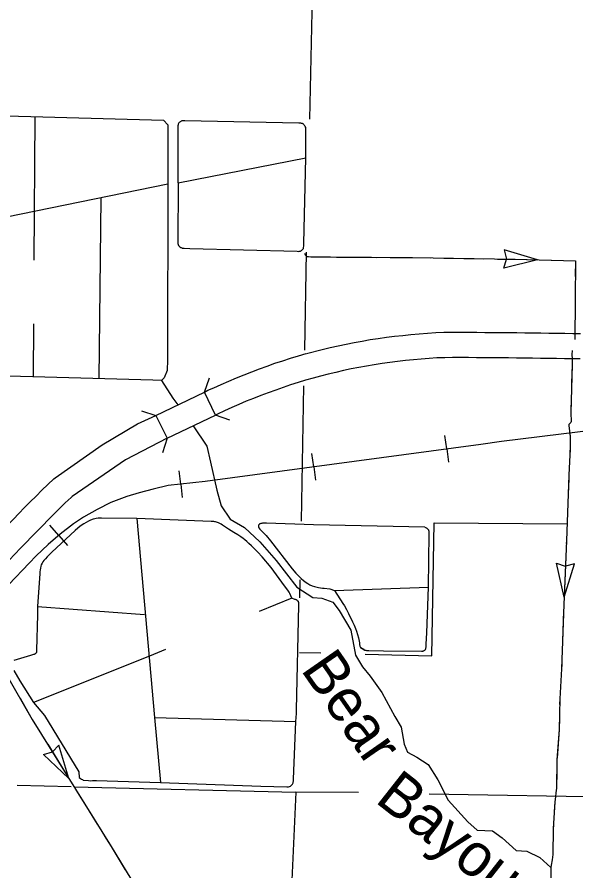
# Model space of a CAD drawing. Extents: x 1196286 to 1268366, y 2040822 to 2082115.
# Drawn here: x 1223139 to 1225200, y 2055546 to 2058695 of the extents above; entities that cross this region are included whole.
import ezdxf

# ---------------------------------------------------------------- set-up
doc = ezdxf.new("R2010")
doc.units = 0
for name, color, linetype in [('60', 7, 'Continuous'), ('62', 7, 'Continuous'), ('63', 7, 'Continuous'), ('Level 70', 7, 'Continuous'), ('Level 76', 7, 'Continuous'), ('Level 81', 7, 'Continuous'), ('Level 84', 7, 'Continuous')]:
    doc.layers.add(name, color=color, linetype=linetype)

msp = doc.modelspace()

# ---------------------------------------------------------------- linework, layer by layer
at = {"layer": '60'}
for points in [[(1224227.9, 2058772.2), (1224217.3, 2058319.1)], [(1224205.7, 2057827.8), (1224198.7, 2057466.5)], [(1224196.2, 2057334.4), (1224186.5, 2056835.4)], [(1224182.3, 2056619.6), (1224181, 2056552.5)], [(1223338.9, 2055856.2), (1223139.9, 2055860.9)], [(1226102.5, 2055804.8), (1224658.8, 2055828.4)]]:
    msp.add_lwpolyline(points, dxfattribs=at)
at = {"layer": '62'}
for points in [[(1222253.8, 2058354.1), (1223679.6, 2058314.3), (1223694.7, 2058298.1), (1223694.9, 2058089.6), (1223694.2, 2057430.3), (1223692.6, 2057391.9), (1223681.3, 2057364.7), (1223671.9, 2057354.8), (1223639.9, 2057355.7), (1222708.7, 2057381.5), (1222720.4, 2057879.5)], [(1223204.6, 2058327.6), (1223201.2, 2057798.8)], [(1224204, 2058175.4), (1224204.8, 2058277.6), (1224204.7, 2058280.9), (1224204.4, 2058284.1), (1224204.2, 2058286.1), (1224203.6, 2058288), (1224202.2, 2058291.3), (1224200.6, 2058294.2), (1224198.6, 2058296.9), (1224196.3, 2058299), (1224193.9, 2058301), (1224192.7, 2058301.6), (1224191.5, 2058302.2), (1224190, 2058302.6), (1224188.5, 2058302.9), (1224185.7, 2058303.2), (1224178.1, 2058303.6), (1223757.9, 2058312.7), (1223752.8, 2058312.9), (1223749.4, 2058312.6), (1223747.2, 2058312.1), (1223744.8, 2058311.2), (1223742.6, 2058310.1), (1223740.9, 2058309.1), (1223739.1, 2058307.7), (1223737.2, 2058305.8), (1223736.1, 2058304.4), (1223734.5, 2058302), (1223733.7, 2058300.1), (1223733.2, 2058297.7), (1223732.7, 2058294), (1223732.5, 2058289.7), (1223732.7, 2058083.6)], [(1223733.2, 2058083.7), (1223731.8, 2057862.9), (1223732.1, 2057860.8), (1223732.3, 2057859.4), (1223733.6, 2057855.9), (1223735.1, 2057853.1), (1223737.4, 2057850.1), (1223740, 2057847.7), (1223742.9, 2057845.5), (1223744.4, 2057844.6), (1223746.3, 2057843.8), (1223748.3, 2057843.1), (1223751.5, 2057842.5), (1223755.3, 2057842.3), (1223776.7, 2057841.8), (1224172.1, 2057831.2), (1224177.4, 2057830.9), (1224180.2, 2057831.1), (1224182.1, 2057831.5), (1224184, 2057832), (1224185.7, 2057832.7), (1224187.6, 2057833.7), (1224189.4, 2057834.9), (1224191.1, 2057836.1), (1224192.4, 2057837.4), (1224193.6, 2057838.8), (1224194.5, 2057840.4), (1224195, 2057841.6), (1224195.7, 2057843.7), (1224196.1, 2057845.8), (1224196.4, 2057849.9), (1224196.9, 2057860.5), (1224203.6, 2058175.3)], [(1223733.2, 2058083.7), (1224203.6, 2058175.3)], [(1223694.9, 2058078.7), (1222720.4, 2057879.5)], [(1223448.1, 2058028.3), (1223441.2, 2057361.2)], [(1223199.7, 2057564.2), (1223198.4, 2057367.9)], [(1223671.9, 2057354.8), (1223713.8, 2057289.9), (1223732, 2057264.3)], [(1223789.1, 2057187.7), (1223838.9, 2057112.5), (1223852.7, 2057052.9), (1223876.2, 2056950.3), (1223891.7, 2056892.2), (1223925.6, 2056843.3), (1223978.4, 2056813.1), (1224035.1, 2056759.9), (1224094.4, 2056690.2), (1224170.4, 2056591.9), (1224229.5, 2056554.9), (1224263.8, 2056551.8), (1224304.1, 2056537), (1224327.3, 2056506.5), (1224370.1, 2056434.4), (1224387.5, 2056341.9), (1224413.4, 2056298.2), (1224441.5, 2056264.2), (1224484.8, 2056204.2), (1224531.8, 2056115.3), (1224556.3, 2056076.5), (1224566.7, 2056013.8), (1224578.6, 2055983.8), (1224613.8, 2055965.9), (1224655.2, 2055937.9), (1224690.5, 2055882.3), (1224729.2, 2055806.9), (1224801.2, 2055726.8), (1224835.9, 2055695.8), (1224893.1, 2055693.3), (1224928, 2055667.3), (1224980.1, 2055620.8), (1225019.4, 2055619.1), (1225067.5, 2055595.7), (1225108.3, 2055558.5)], [(1223580.4, 2056845.3), (1223450.3, 2056846.5), (1223442.8, 2056846.9), (1223438.3, 2056846.6), (1223431.4, 2056845.8), (1223425.5, 2056844.7), (1223419.7, 2056843.1), (1223409.9, 2056839.8), (1223402.9, 2056835.7), (1223393.5, 2056831.1), (1223386.1, 2056826.6), (1223371.8, 2056817.1), (1223353.1, 2056801.4), (1223267.1, 2056721.4), (1223254.9, 2056709.5), (1223249.9, 2056703.8), (1223243.9, 2056697.4), (1223237.9, 2056690.3), (1223234.5, 2056686), (1223231.4, 2056680.8), (1223228.7, 2056674.6), (1223227, 2056669.7), (1223225.8, 2056662.7), (1223224.8, 2056656.9), (1223223.7, 2056648.4), (1223223.4, 2056642.5), (1223215, 2056520.8)], [(1224152.6, 2056551.6), (1224144.8, 2056568.8), (1224142.2, 2056574), (1224139.9, 2056578), (1224137.8, 2056581.1), (1224125, 2056597.7), (1224076.2, 2056665.4), (1224043.4, 2056704.5), (1224027.4, 2056721.3), (1224003.7, 2056745.1), (1223994.4, 2056753.8), (1223987, 2056760.7), (1223979, 2056767.2), (1223973, 2056771.7), (1223964.5, 2056777.9), (1223953.6, 2056785), (1223938.3, 2056794.3), (1223918.5, 2056806.1), (1223896.5, 2056821.6), (1223891.7, 2056824.8), (1223887.5, 2056827.3), (1223882.2, 2056829.5), (1223878.7, 2056830.8), (1223874.4, 2056832.2), (1223870.9, 2056833), (1223868.1, 2056833.6), (1223864.4, 2056834.1), (1223860.3, 2056834.4), (1223855.4, 2056834.5), (1223580.4, 2056845.3)], [(1223580.4, 2056845.3), (1223646.3, 2056111.4), (1223668.4, 2055871.7)], [(1224643.2, 2056813.5), (1224232.3, 2056822.4), (1224058.7, 2056828), (1224048.6, 2056828.3), (1224044.7, 2056828.1), (1224041.6, 2056827.8), (1224038.5, 2056827.2), (1224035.7, 2056826.3), (1224034.2, 2056825.5), (1224032.6, 2056824.4), (1224031.6, 2056823.5), (1224030.4, 2056822.2), (1224029.8, 2056821), (1224029.4, 2056819.3), (1224029.3, 2056817.9), (1224029.3, 2056816.4), (1224029.4, 2056815), (1224029.9, 2056813.5), (1224030.6, 2056811.9), (1224031.4, 2056810.8), (1224035, 2056806.2), (1224049.5, 2056792.1), (1224058.1, 2056782.4), (1224074.3, 2056763.6), (1224154, 2056660.5), (1224167.6, 2056644.6), (1224178.4, 2056633.2), (1224187, 2056624.7), (1224195.5, 2056617.1), (1224204.9, 2056609.9), (1224211.6, 2056605.6), (1224219.1, 2056601.5), (1224227.3, 2056597.9), (1224236.3, 2056594.8), (1224245.4, 2056592.1), (1224251, 2056590.8), (1224257.9, 2056589.7), (1224265.4, 2056588.8), (1224272.2, 2056588.4), (1224293, 2056585.9), (1224310.2, 2056579.7)], [(1224656.5, 2056592.4), (1224659, 2056789.5), (1224659, 2056793.4), (1224659.1, 2056795.6), (1224658.9, 2056797.2), (1224658.8, 2056798.5), (1224658.4, 2056799.7), (1224658.1, 2056801), (1224657.2, 2056802.5), (1224656.3, 2056803.9), (1224655.4, 2056805), (1224654.7, 2056806), (1224653, 2056807.6), (1224651.5, 2056808.7), (1224648.9, 2056810.4), (1224647.7, 2056811), (1224646.2, 2056811.7), (1224643.8, 2056812.3)], [(1224310.2, 2056579.7), (1224656.5, 2056592.4)], [(1224310.2, 2056579.7), (1224341.2, 2056532.4), (1224346.2, 2056523.9), (1224353.7, 2056510.4), (1224361.2, 2056495.2), (1224376.8, 2056464.4), (1224382.4, 2056451.7), (1224387, 2056440.3), (1224390.9, 2056429.7), (1224398, 2056405.6), (1224401.5, 2056387.2), (1224402.7, 2056380.2), (1224403.1, 2056377.7), (1224403.7, 2056375.1), (1224404.5, 2056372.1), (1224405.3, 2056369.8), (1224405.4, 2056369.6)], [(1224417.8, 2056363.4), (1224418.8, 2056362.6), (1224405.4, 2056369.6), (1224422, 2056360.6), (1224423, 2056360.2), (1224423.6, 2056360), (1224425.9, 2056359.6), (1224428.5, 2056359.4), (1224437, 2056359.1), (1224490.6, 2056358.2), (1224630.8, 2056356.5), (1224633.5, 2056356.6), (1224635.4, 2056356.7), (1224636.8, 2056357), (1224637.8, 2056357.2), (1224639.1, 2056357.8), (1224640.1, 2056358.3), (1224642.5, 2056359.6), (1224643.4, 2056360.4), (1224644.1, 2056361), (1224645.4, 2056362.8), (1224645.9, 2056363.7), (1224646.4, 2056364.6), (1224646.9, 2056366.6), (1224647.2, 2056368.6), (1224647.5, 2056370.8), (1224648, 2056382.2), (1224650, 2056423.6), (1224656.5, 2056592.4)], [(1224152.6, 2056551.6), (1224032.1, 2056502.7)], [(1224167.4, 2056097.3), (1224169.6, 2056126.7), (1224169.7, 2056140.3), (1224178.1, 2056525.9), (1224178.1, 2056531.3), (1224177.8, 2056534.5), (1224177.2, 2056537.8), (1224176.6, 2056539.2), (1224175.9, 2056540.3), (1224175, 2056541.4), (1224174, 2056542.5), (1224173, 2056543.5), (1224171.6, 2056544.5), (1224170.2, 2056545.2), (1224168.7, 2056545.8), (1224166.2, 2056546.5), (1224163.7, 2056546.8), (1224152.6, 2056551.6)], [(1223215, 2056520.8), (1223214.3, 2056489.8), (1223210.9, 2056359.7), (1223210.9, 2056357.1), (1223210.9, 2056354.5), (1223210.6, 2056352.3), (1223210.4, 2056351.4), (1223210, 2056350.6), (1223209.4, 2056349.6), (1223208.8, 2056348.8), (1223207.6, 2056347.5), (1223206, 2056346.2), (1223204.8, 2056345.4), (1223203.6, 2056344.9), (1223201.8, 2056344.3), (1223199.7, 2056343.7), (1223188.2, 2056340.2), (1223127.6, 2056322.2)], [(1223215, 2056520.8), (1223609.1, 2056491.6)], [(1223687, 2056362.8), (1223627.2, 2056338.5), (1223200, 2056166.7)], [(1223127, 2056284.9), (1223150, 2056246.7), (1223200, 2056166.7)], [(1223200, 2056166.7), (1223240.7, 2056119.6), (1223367.6, 2055911.3), (1223368.7, 2055891), (1223373.5, 2055886.8), (1223376.6, 2055884.7), (1223380.2, 2055882.6), (1223383.6, 2055881.1), (1223402.6, 2055879.4), (1223409.3, 2055878.3), (1223417.7, 2055879.4), (1223432.2, 2055878.8), (1223668.4, 2055871.7)], [(1223646.3, 2056111.4), (1224167.4, 2056097.3)], [(1223668.4, 2055871.7), (1224038.5, 2055859), (1224134.5, 2055855.5), (1224137.8, 2055855.7), (1224140.8, 2055856), (1224144.2, 2055857), (1224147.1, 2055858.5), (1224149.4, 2055860.2), (1224152.3, 2055862.9), (1224155, 2055866), (1224156.3, 2055868.7), (1224157.2, 2055871.1), (1224157.9, 2055873.9), (1224158.4, 2055877.5), (1224159.1, 2055884.7), (1224167.4, 2056097.3)]]:
    msp.add_lwpolyline(points, dxfattribs=at)
at = {"layer": '63'}
for p, q in [((1225059.1, 2057799.7), (1224935.6, 2057836)), ((1224935.6, 2057836), (1224943.7, 2057802.7)), ((1224934, 2057769.4), (1224943.7, 2057802.2)), ((1225059.1, 2057799.7), (1224934, 2057769.4)), ((1225156.6, 2056555.1), (1225128.4, 2056680.6)), ((1225128.4, 2056680.6), (1225161.1, 2056670.4)), ((1225156.6, 2056555.1), (1225195, 2056677.9)), ((1225195, 2056677.9), (1225161.6, 2056670.4)), ((1223293.2, 2056010.1), (1223269.8, 2055985.1)), ((1223330.4, 2055886.9), (1223293.2, 2056010.1)), ((1223236.6, 2055974.9), (1223269.4, 2055984.9)), ((1223330.4, 2055886.9), (1223236.6, 2055974.9))]:
    msp.add_line(p, q, dxfattribs=at)
for points in [[(1222238.3, 2057849.1), (1222340.3, 2057647.8), (1222582.2, 2057162.5), (1222832.4, 2056669.9), (1222880.1, 2056582), (1222911.4, 2056510.2), (1222916.1, 2056499.7), (1222922.5, 2056489.1), (1222932.1, 2056474.1), (1222949.3, 2056454.5), (1223043.5, 2056348.3), (1223076.7, 2056303), (1223095.4, 2056278.2), (1223195.3, 2056104.7), (1223486, 2055636.2), (1223776.3, 2055159.1)], [(1224199, 2057824.4), (1224200.3, 2057821.4), (1224201.9, 2057818.4), (1224204.1, 2057816), (1224206.6, 2057813.8), (1224209.3, 2057812.6), (1224213.9, 2057811.7), (1224223.1, 2057811.1), (1224294.8, 2057810.2), (1224598, 2057807.8), (1224975.6, 2057801.7), (1225198.4, 2057796.4), (1225196.2, 2057506)], [(1224199, 2057824.4), (1224200.3, 2057821.4), (1224201.9, 2057818.4), (1224204.1, 2057816), (1224206.6, 2057813.8), (1224209.3, 2057812.6), (1224213.9, 2057811.7), (1224223.1, 2057811.1), (1224267.2, 2057810.6)], [(1224316.7, 2057810), (1224465.2, 2057808.8)], [(1224514.6, 2057808.5), (1224598, 2057807.8), (1224663.1, 2057806.7)], [(1224712.6, 2057805.9), (1224861.1, 2057803.5)], [(1224910.6, 2057802.7), (1224975.6, 2057801.7), (1225059.1, 2057799.7)], [(1225108.6, 2057798.5), (1225198.4, 2057796.4), (1225197.9, 2057737.7)], [(1225197.6, 2057688.2), (1225197, 2057614)], [(1225197, 2057614), (1225196.4, 2057539.7)], [(1225185.8, 2057464.9), (1225185.7, 2057450.5), (1225186.4, 2057434.4), (1225186.2, 2057413.5), (1225181.4, 2057234.8), (1225183.2, 2057203.3), (1225181.9, 2057199.8), (1225177, 2057195.1), (1225174.6, 2057191.9), (1225174.2, 2057188.8), (1225179, 2057147.5), (1225179.5, 2057134.7), (1225179.4, 2057117.7), (1225177.5, 2057080.1), (1225174.7, 2057004.9), (1225165.1, 2056762.9), (1225155.5, 2056528.1), (1225147.4, 2056291.7), (1225140.6, 2056181), (1225138.2, 2056067.4), (1225130.2, 2055955.6), (1225128.1, 2055850.9), (1225126.6, 2055834.3), (1225125.1, 2055819.4), (1225122.7, 2055800.9), (1225116.8, 2055701.6), (1225114.8, 2055606.2), (1225112.8, 2055587.2), (1225109.1, 2055567.5), (1225108.3, 2055558.5), (1225107.6, 2055550.6), (1225109.5, 2055482.1)], [(1225186.4, 2057434.5), (1225186.2, 2057413.5), (1225184.3, 2057343.1)], [(1225183, 2057293.6), (1225181.4, 2057234.8), (1225183.2, 2057203.3), (1225181.9, 2057199.8), (1225177, 2057195.1), (1225174.6, 2057191.9), (1225174.2, 2057188.8), (1225178.9, 2057148.6)], [(1225178.5, 2057099.1), (1225177.5, 2057080.1), (1225174.7, 2057004.9), (1225172.5, 2056950.7)], [(1225170.6, 2056901.3), (1225165.1, 2056762.9), (1225164.7, 2056752.9)], [(1225162.7, 2056703.4), (1225156.6, 2056555.1)], [(1225154.7, 2056505.6), (1225152.2, 2056431.4)], [(1225152.2, 2056431.4), (1225149.6, 2056357.2)], [(1225147.9, 2056307.7), (1225147.4, 2056291.7), (1225140.6, 2056181), (1225140.2, 2056159.4)], [(1223150.3, 2056182.8), (1223195.3, 2056104.7), (1223226.1, 2056055.1)], [(1225139.1, 2056109.9), (1225138.2, 2056067.4), (1225130.6, 2055961.7)], [(1223252.2, 2056013.1), (1223330.4, 2055886.9)], [(1225129.3, 2055912.3), (1225128.1, 2055850.9), (1225126.6, 2055834.3), (1225125.1, 2055819.4), (1225122.7, 2055800.9), (1225120.5, 2055764.1)], [(1223356.5, 2055844.8), (1223395.7, 2055781.7)], [(1223395.7, 2055781.7), (1223434.8, 2055718.6)], [(1225117.6, 2055714.7), (1225116.8, 2055701.6), (1225114.8, 2055606.2), (1225112.8, 2055587.2), (1225109.1, 2055567.5), (1225109, 2055566.7)], [(1223460.9, 2055676.6), (1223486, 2055636.2), (1223538.5, 2055549.9)]]:
    msp.add_lwpolyline(points, dxfattribs=at)
at = {"layer": 'Level 70'}
for points in [[(1224423.6, 2056345.3), (1224669.4, 2056338.6), (1224677.9, 2056830.2), (1225167.6, 2056826)], [(1224181, 2056351.8), (1224259.7, 2056349.7)], [(1223349.7, 2055855.9), (1224167.1, 2055836.5), (1224145.6, 2055349.4), (1223655.5, 2055357.6)], [(1224397.9, 2055835.3), (1224167.1, 2055836.5)]]:
    msp.add_lwpolyline(points, dxfattribs=at)
at = {"layer": 'Level 76'}
for points in [[(1223830.4, 2057311.3), (1223849, 2057364.4)], [(1223597.6, 2057243.3), (1223650.9, 2057225.5)], [(1223924.1, 2057208.2), (1223871, 2057226.8)], [(1223692.9, 2057141.7), (1223675.2, 2057088.4)]]:
    msp.add_lwpolyline(points, dxfattribs=at)
at = {"layer": 'Level 81'}
for p, q in [((1224724, 2057102.2), (1224717.4, 2057151.3)), ((1224233.4, 2057036.3), (1224226.8, 2057085.4)), ((1224724, 2057102.2), (1224730.6, 2057053.1)), ((1223742.6, 2056972.2), (1223737, 2057021.4)), ((1224233.4, 2057036.3), (1224240, 2056987.2)), ((1223742.6, 2056972.2), (1223748.2, 2056923)), ((1223292.9, 2056783.5), (1223260.3, 2056820.7)), ((1223292.9, 2056783.5), (1223325.4, 2056746.2))]:
    msp.add_line(p, q, dxfattribs=at)
for points in [[(1226196.5, 2057294), (1226017.8, 2057272.2), (1225505.6, 2057201.4), (1224925.9, 2057130), (1224850, 2057119.1), (1223833, 2056982.5)], [(1225505.6, 2057201.4), (1224925.9, 2057130), (1224850, 2057119.1), (1223833, 2056982.5), (1223696, 2056966.9), (1223640.9, 2056953.8), (1223590, 2056940.6), (1223544.1, 2056927.1), (1223485.6, 2056904.9), (1223434.1, 2056879.4), (1223384.5, 2056850.6), (1223347.5, 2056825.5), (1223298.6, 2056788.5), (1223253.7, 2056749.2), (1223209.8, 2056707.9), (1223184, 2056681.2), (1222958.3, 2056444.6), (1222746.4, 2056228.4), (1222687.7, 2056167.5), (1222553, 2056025.1), (1222392.9, 2055865.3), (1222263.7, 2055729.9), (1221921.5, 2055367.5), (1221297.2, 2054718.3)], [(1223833, 2056982.5), (1223696, 2056966.9), (1223640.9, 2056953.8), (1223590, 2056940.6), (1223544.1, 2056927.1), (1223485.6, 2056904.9), (1223434.1, 2056879.4), (1223384.5, 2056850.6), (1223347.5, 2056825.5), (1223298.6, 2056788.5), (1223253.7, 2056749.2), (1223209.8, 2056707.9), (1223184, 2056681.2), (1222958.3, 2056444.6), (1222746.4, 2056228.4), (1222687.7, 2056167.5), (1222553, 2056025.1), (1222392.9, 2055865.3), (1222263.7, 2055729.9), (1221921.5, 2055367.5), (1221297.2, 2054718.3), (1221098, 2054516.8), (1220476.4, 2053874.3), (1220162.2, 2053549.3)]]:
    msp.add_lwpolyline(points, dxfattribs=at)
at = {"layer": 'Level 84'}
for points in [[(1224206.1, 2057453.9), (1224264.6, 2057469.2), (1224294, 2057475.9), (1224323.1, 2057482.5), (1224352.5, 2057488.9), (1224382.1, 2057494.8), (1224411.8, 2057500.2), (1224441.5, 2057505.3), (1224471.5, 2057510), (1224501.5, 2057514.1), (1224531.7, 2057517.9), (1224561.8, 2057521.2), (1224591.9, 2057524.2), (1224622, 2057527), (1224652.4, 2057529.5), (1224683, 2057531.4), (1224713.7, 2057532.6), (1224744.2, 2057533), (1224774.5, 2057533.2), (1224804.6, 2057532.9), (1224834.3, 2057532.6), (1224863.8, 2057532.3), (1224893.3, 2057532.1), (1224923, 2057531.9), (1224952.5, 2057531.5), (1224982.1, 2057531.3), (1225011.8, 2057530.8), (1225041.3, 2057530.4), (1225070.9, 2057529.9), (1225100.5, 2057529.5), (1225130.1, 2057529.1), (1225159.6, 2057528.7), (1225188.8, 2057528.3), (1225217.4, 2057528)], [(1223871, 2057226.8), (1223830.4, 2057311.3), (1223843, 2057318.6), (1223864.8, 2057327.8), (1223892.4, 2057340.5), (1223920.4, 2057352.8), (1223948.6, 2057364.6), (1223976.8, 2057375.9), (1224005, 2057386.8), (1224033, 2057397.4), (1224061.3, 2057407.8), (1224090, 2057418), (1224118.9, 2057427.6), (1224147.8, 2057436.8), (1224176.8, 2057445.5), (1224205.5, 2057453.7)], [(1225216.4, 2057434.2), (1225187.5, 2057434.5), (1225158.3, 2057435), (1225128.9, 2057435.4), (1225099.3, 2057435.7), (1225069.5, 2057436.2), (1225039.9, 2057436.6), (1225010.3, 2057437.1), (1224981, 2057437.5), (1224951.5, 2057437.8), (1224922, 2057438.1), (1224892.7, 2057438.4), (1224863.1, 2057438.5), (1224833.4, 2057438.8), (1224803.7, 2057439.1), (1224774.2, 2057439.4), (1224745.1, 2057439.3), (1224716.3, 2057438.8), (1224687.7, 2057437.7), (1224659, 2057435.9), (1224630.1, 2057433.6), (1224600.9, 2057430.9), (1224571.6, 2057428), (1224542.7, 2057424.8), (1224513.8, 2057421.2), (1224485.1, 2057417.2), (1224456.6, 2057412.8), (1224428.1, 2057407.9), (1224399.8, 2057402.7), (1224371.6, 2057397.1), (1224343.3, 2057391), (1224314.9, 2057384.5), (1224286.6, 2057378), (1224258.8, 2057371), (1224231.3, 2057363.6)], [(1224231.3, 2057363.6), (1224203.2, 2057355.5), (1224175.5, 2057347.2), (1224147.9, 2057338.4), (1224120.4, 2057329.3), (1224093.2, 2057319.6), (1224065.8, 2057309.5), (1224038.3, 2057299.2), (1224011.1, 2057288.7), (1223984.2, 2057277.9), (1223957.4, 2057266.6), (1223930.9, 2057255), (1223904.5, 2057242.9), (1223878.3, 2057230.4), (1223871, 2057226.8)], [(1223650.9, 2057225.5), (1223830.4, 2057311.3)], [(1222962.5, 2056674.2), (1222978, 2056690.2), (1222999.7, 2056712.7), (1223021.2, 2056735.3), (1223042.8, 2056757.6), (1223064, 2056779.5), (1223084.7, 2056801), (1223105.2, 2056822.4), (1223125.7, 2056843.5), (1223146.1, 2056864.5), (1223166.8, 2056885.8), (1223187.8, 2056907.2), (1223209.1, 2056928.6), (1223230.7, 2056949.9), (1223252.7, 2056971), (1223275, 2056991.8), (1223279.9, 2056996.2), (1223452.9, 2057117.3), (1223583.9, 2057194.3), (1223650.9, 2057225.5)], [(1223650.9, 2057225.5), (1223692.9, 2057141.7), (1223539, 2057062.6), (1223342.7, 2056926.6), (1223338.4, 2056922.7), (1223317.1, 2056902.9), (1223296.1, 2056882.7), (1223275.2, 2056862.1), (1223254.4, 2056841.2), (1223233.8, 2056820.3), (1223213.3, 2056799.1), (1223192.9, 2056778.2), (1223172.7, 2056757.3), (1223152.3, 2056736), (1223131.4, 2056714.3), (1223110.2, 2056692.5), (1223088.9, 2056670.3), (1223067.3, 2056647.8), (1223045.4, 2056625), (1223029.8, 2056609), (1222962.5, 2056674.2)], [(1223692.9, 2057141.7), (1223871, 2057226.8)]]:
    msp.add_lwpolyline(points, dxfattribs=at)

# ---------------------------------------------------------------- texts
at = {"layer": '62'}
for s, rotation, p in [('Bear', 304.8321, (1224182.9, 2056288.5)), ('Bayou', 321.8285, (1224455.1, 2055802.4))]:
    msp.add_text(s, height=158.4, rotation=rotation, dxfattribs=at).set_placement(p)

doc.saveas('drawing.dxf')
